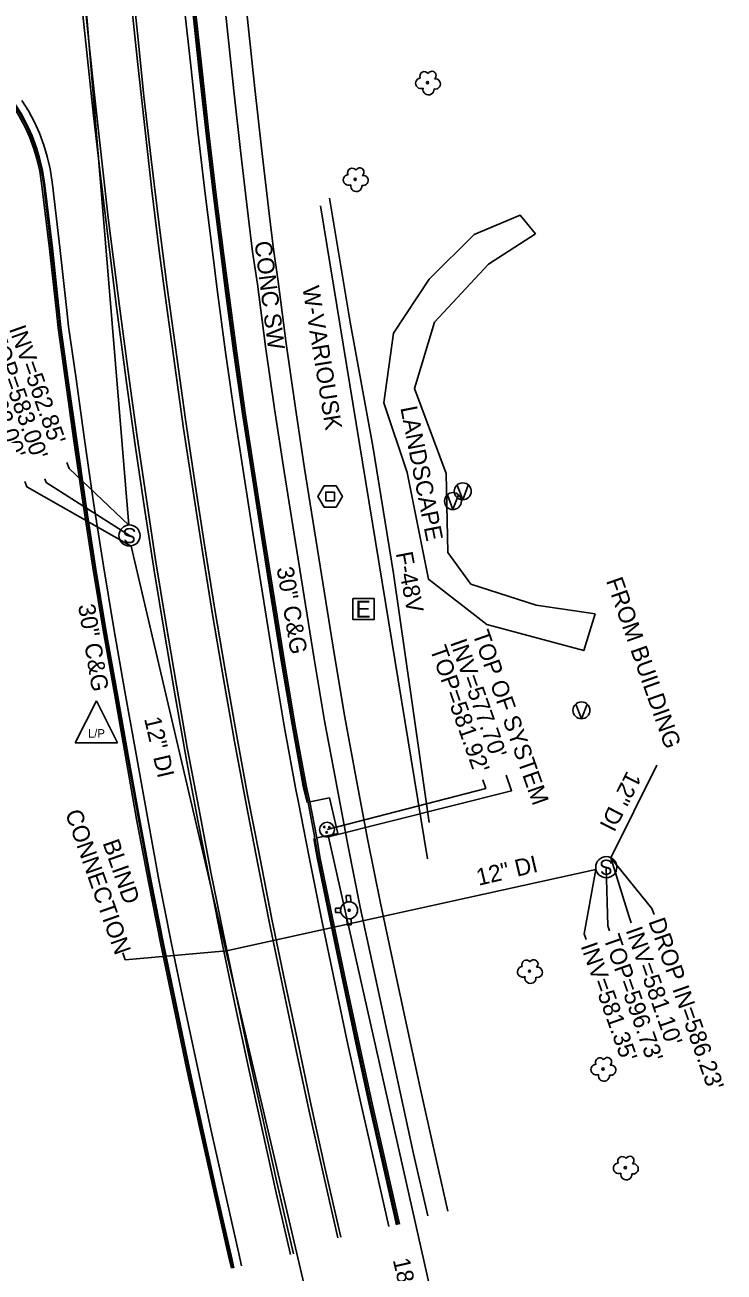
# Model space of a CAD drawing. Extents: x 2004847 to 2009016, y 1134161 to 1140101.
# Drawn here: x 2007523.7 to 2007689.1, y 1136946.2 to 1137241.2 of the extents above; entities that cross this region are included whole.
import ezdxf

# ---------------------------------------------------------------- set-up
doc = ezdxf.new("R2010")
doc.units = 0
for name, color, linetype in [('RD_EX_BldgApp', 7, 'Continuous'), ('RD_EX_Conc', 7, 'Continuous'), ('RD_EX_Curb', 7, 'Continuous'), ('RD_EX_DR_Inlet', 7, 'Continuous'), ('RD_EX_DR_Inlet_txCode', 7, 'Continuous'), ('RD_EX_DR_Pipe', 7, 'Continuous'), ('RD_EX_DR_Pipe_txCode', 7, 'Continuous'), ('RD_EX_Fence_Other', 7, 'Continuous'), ('RD_EX_Pavement_Markings', 7, 'Continuous'), ('RD_EX_Road', 7, 'Continuous'), ('RD_EX_SU_Elec', 7, 'Continuous'), ('RD_EX_SU_Sewer', 7, 'Continuous'), ('RD_EX_UT', 7, 'Continuous'), ('RD_EX_VEG', 7, 'Continuous'), ('RD_Sketch2', 7, 'Continuous'), ('RD_Sketch3', 7, 'Continuous')]:
    doc.layers.add(name, color=color, linetype=linetype)

msp = doc.modelspace()

# ---------------------------------------------------------------- linework, layer by layer
at = {"layer": 'RD_EX_BldgApp'}
msp.add_line((2007593.63, 1137198.39), (2007618.92, 1137043.93), dxfattribs=at)
at = {"layer": 'RD_EX_Conc'}
for points in [[(2007558.31, 1137480.41), (2007558.45, 1137464.24), (2007558.81, 1137449.33), (2007559.15, 1137434.3), (2007559.62, 1137419.34), (2007560.18, 1137404.46), (2007560.79, 1137389.52), (2007561.42, 1137374.51), (2007562.14, 1137359.65), (2007562.95, 1137344.71), (2007563.94, 1137329.81), (2007564.94, 1137314.87), (2007565.97, 1137299.95), (2007567.23, 1137285.11), (2007568.58, 1137270.25), (2007569.98, 1137255.36), (2007571.54, 1137240.53), (2007573.09, 1137225.63), (2007574.74, 1137210.79), (2007576.47, 1137195.99), (2007577.55, 1137187.51)], [(2007563.28, 1137480.5), (2007563.48, 1137464.33), (2007563.84, 1137449.47), (2007564.18, 1137434.42), (2007564.65, 1137419.48), (2007565.21, 1137404.66), (2007565.82, 1137389.74), (2007566.45, 1137374.72), (2007567.17, 1137359.93), (2007567.96, 1137345.01), (2007568.94, 1137330.15), (2007569.95, 1137315.22), (2007570.98, 1137300.32), (2007572.22, 1137285.54), (2007573.56, 1137270.71), (2007574.96, 1137255.84), (2007576.52, 1137241.07), (2007578.07, 1137226.17), (2007579.71, 1137211.37), (2007581.44, 1137196.62), (2007582.52, 1137188.15)], [(2007582.52, 1137188.15), (2007583.58, 1137180.52), (2007585.5, 1137165.85), (2007587.61, 1137151.12), (2007589.83, 1137136.3), (2007592.18, 1137121.52), (2007594.54, 1137106.79), (2007596.91, 1137092.03), (2007599.35, 1137077.45), (2007602.04, 1137062.9), (2007604.81, 1137048.24), (2007607.82, 1137033.46), (2007610.88, 1137019.01), (2007614.04, 1137004.33), (2007617.22, 1136989.76), (2007620.42, 1136975.26), (2007623.73, 1136960.59)], [(2007577.55, 1137187.51), (2007578.71, 1137179.88), (2007580.64, 1137165.14), (2007582.76, 1137150.37), (2007584.99, 1137135.55), (2007587.37, 1137120.76), (2007589.74, 1137106), (2007592.14, 1137091.23), (2007594.58, 1137076.58), (2007597.28, 1137061.96), (2007600.06, 1137047.28), (2007603.03, 1137032.52), (2007606.11, 1137017.99), (2007609.27, 1137003.32), (2007612.43, 1136988.72), (2007615.64, 1136974.17), (2007618.96, 1136959.52)]]:
    msp.add_lwpolyline(points, dxfattribs=at)
at = {"layer": 'RD_EX_Curb'}
for points in [[(2007550.81, 1137479.12), (2007551.12, 1137464.1), (2007551.5, 1137449.1), (2007551.98, 1137438.47), (2007552.01, 1137429.88), (2007552.15, 1137424.54), (2007552.7, 1137409.6), (2007553.29, 1137394.72), (2007553.95, 1137379.73), (2007554.58, 1137364.86), (2007555.4, 1137349.97), (2007556.32, 1137334.99), (2007557.25, 1137320.19), (2007558.28, 1137305.15), (2007559.41, 1137290.45), (2007560.7, 1137275.43), (2007562.08, 1137260.68), (2007563.51, 1137245.88), (2007565.14, 1137231.01), (2007566.76, 1137216.22), (2007568.45, 1137201.47), (2007570.35, 1137186.59)], [(2007551.27, 1137479.12), (2007551.55, 1137464.1), (2007551.87, 1137449.11), (2007552.45, 1137438.48), (2007552.45, 1137429.9), (2007552.6, 1137424.55), (2007553.12, 1137409.62), (2007553.7, 1137394.74), (2007554.33, 1137379.75), (2007554.95, 1137364.88), (2007555.78, 1137349.99), (2007556.71, 1137335.02), (2007557.64, 1137320.22), (2007558.68, 1137305.17), (2007559.77, 1137290.48), (2007561.07, 1137275.46), (2007562.46, 1137260.71), (2007563.92, 1137245.92), (2007565.54, 1137231.05), (2007567.15, 1137216.27), (2007568.87, 1137201.52), (2007570.75, 1137186.64)], [(2007551.87, 1137429.88), (2007551.87, 1137428.58), (2007551.89, 1137424.53), (2007552.41, 1137409.59), (2007552.99, 1137394.7), (2007553.66, 1137379.72), (2007554.31, 1137364.85), (2007555.14, 1137349.95), (2007556.04, 1137334.98), (2007556.98, 1137320.17), (2007558.02, 1137305.13), (2007559.1, 1137290.43), (2007560.47, 1137275.42), (2007561.84, 1137260.66), (2007563.26, 1137245.85), (2007564.86, 1137230.98), (2007566.47, 1137216.19), (2007568.19, 1137201.44), (2007570.08, 1137186.56)], [(2007489.11, 1137238.88), (2007490.91, 1137238.71), (2007493.9, 1137238.39), (2007496.5, 1137237.98), (2007499.11, 1137237.45), (2007501.98, 1137236.61), (2007504.36, 1137235.61), (2007506.81, 1137234.47), (2007509.43, 1137233), (2007511.35, 1137231.71), (2007513.36, 1137230.22), (2007515.59, 1137228.2), (2007517.5, 1137226.19), (2007519.11, 1137224.37), (2007520.88, 1137221.94), (2007522.34, 1137219.64), (2007523.74, 1137216.99), (2007524.75, 1137214.69), (2007525.78, 1137211.87), (2007526.48, 1137209.5), (2007527.2, 1137206.58), (2007527.73, 1137203.15)], [(2007489.14, 1137239.31), (2007490.96, 1137239.14), (2007493.95, 1137238.82), (2007496.59, 1137238.41), (2007499.24, 1137237.89), (2007502.12, 1137237.04), (2007504.53, 1137236.03), (2007507.02, 1137234.87), (2007509.64, 1137233.4), (2007511.62, 1137232.08), (2007513.68, 1137230.54), (2007515.91, 1137228.52), (2007517.83, 1137226.49), (2007519.47, 1137224.6), (2007521.26, 1137222.19), (2007522.73, 1137219.85), (2007524.13, 1137217.2), (2007525.18, 1137214.85), (2007526.21, 1137212.03), (2007526.91, 1137209.59), (2007527.6, 1137206.67), (2007528.15, 1137203.2)], [(2007489.15, 1137239.52), (2007490.99, 1137239.37), (2007493.97, 1137239.05), (2007496.63, 1137238.64), (2007499.28, 1137238.05), (2007502.16, 1137237.21), (2007504.6, 1137236.18), (2007507.1, 1137235.02), (2007509.72, 1137233.56), (2007511.73, 1137232.21), (2007513.8, 1137230.66), (2007516.05, 1137228.67), (2007517.98, 1137226.63), (2007519.64, 1137224.72), (2007521.44, 1137222.31), (2007522.93, 1137219.96), (2007524.34, 1137217.32), (2007525.39, 1137214.93), (2007526.42, 1137212.12), (2007527.13, 1137209.64), (2007527.87, 1137206.73), (2007528.4, 1137203.23)], [(2007531.16, 1137173.35), (2007529.48, 1137188.26), (2007527.73, 1137203.15)], [(2007531.59, 1137173.4), (2007529.87, 1137188.3), (2007528.15, 1137203.2)], [(2007531.82, 1137173.43), (2007530.23, 1137188.35), (2007528.4, 1137203.23)], [(2007570.08, 1137186.56), (2007571.06, 1137178.88), (2007573, 1137164.06), (2007575.14, 1137149.3), (2007577.41, 1137134.59), (2007579.71, 1137119.81), (2007582.02, 1137105.14), (2007584.42, 1137090.4), (2007586.87, 1137075.69), (2007589.52, 1137061.12), (2007590.47, 1137057.26)], [(2007570.35, 1137186.59), (2007571.34, 1137178.92), (2007573.32, 1137164.11), (2007575.43, 1137149.34), (2007577.7, 1137134.64), (2007579.99, 1137119.85), (2007582.33, 1137105.2), (2007584.72, 1137090.45), (2007587.12, 1137075.74), (2007589.8, 1137061.17), (2007590.66, 1137057.3), (2007592.28, 1137048.81), (2007593.09, 1137044.33), (2007596.05, 1137029.8), (2007599.16, 1137015.16), (2007602.25, 1137000.49), (2007605.43, 1136985.94), (2007608.75, 1136971.39), (2007611.9, 1136957.47)], [(2007570.75, 1137186.64), (2007571.76, 1137178.98), (2007573.72, 1137164.16), (2007575.83, 1137149.4), (2007578.09, 1137134.69), (2007580.36, 1137119.91), (2007582.72, 1137105.26), (2007585.1, 1137090.52), (2007587.52, 1137075.81), (2007590.2, 1137061.25), (2007591.09, 1137057.38), (2007592.71, 1137048.9), (2007593.49, 1137044.41), (2007596.44, 1137029.88), (2007599.54, 1137015.24), (2007602.64, 1137000.57), (2007605.81, 1136986.03), (2007609.11, 1136971.48), (2007612.26, 1136957.55)], [(2007572.55, 1136947.08), (2007571.87, 1136950), (2007568.52, 1136964.72), (2007565.21, 1136979.42), (2007562.02, 1136994.13), (2007558.91, 1137008.94), (2007555.85, 1137023.69), (2007552.92, 1137038.51), (2007550.12, 1137053.33), (2007547.48, 1137068.23), (2007544.86, 1137083.08), (2007542.23, 1137097.99), (2007539.78, 1137112.84), (2007537.5, 1137127.85), (2007535.3, 1137142.79), (2007533.25, 1137157.66), (2007531.57, 1137169.55), (2007531.16, 1137173.35)], [(2007572.86, 1136947.15), (2007572.17, 1136950.07), (2007568.83, 1136964.79), (2007565.56, 1136979.49), (2007562.39, 1136994.21), (2007559.28, 1137009.02), (2007556.24, 1137023.77), (2007553.32, 1137038.58), (2007550.54, 1137053.4), (2007547.85, 1137068.3), (2007545.22, 1137083.15), (2007542.59, 1137098.05), (2007540.14, 1137112.9), (2007537.86, 1137127.9), (2007535.69, 1137142.84), (2007533.59, 1137157.71), (2007531.92, 1137169.6), (2007531.59, 1137173.4)], [(2007573.13, 1136947.22), (2007572.46, 1136950.14), (2007569.11, 1136964.86), (2007565.83, 1136979.55), (2007562.66, 1136994.27), (2007559.53, 1137009.07), (2007556.51, 1137023.82), (2007553.58, 1137038.63), (2007550.81, 1137053.45), (2007548.13, 1137068.35), (2007545.5, 1137083.19), (2007542.87, 1137098.09), (2007540.42, 1137112.94), (2007538.1, 1137127.94), (2007535.96, 1137142.88), (2007533.86, 1137157.74), (2007532.18, 1137169.64), (2007531.82, 1137173.43)], [(2007592.05, 1137048.77), (2007592.82, 1137044.28), (2007595.8, 1137029.74), (2007598.87, 1137015.1), (2007601.96, 1137000.43), (2007605.13, 1136985.88), (2007608.46, 1136971.33), (2007611.61, 1136957.4)]]:
    msp.add_lwpolyline(points, dxfattribs=at)
at = {"layer": 'RD_EX_DR_Inlet'}
msp.add_lwpolyline([(2007592.71, 1137048.9), (2007597.7, 1137049.94), (2007595.74, 1137058.34), (2007591.09, 1137057.38)], dxfattribs=at)
for centre, radius in [((2007595.16, 1137050.85), 1.75), ((2007594.49, 1137051.48), 0.175), ((2007595.07, 1137050.19), 0.175), ((2007595.72, 1137051.41), 0.175)]:
    msp.add_circle(centre, radius, dxfattribs=at)
at = {"layer": 'RD_EX_DR_Inlet_txCode'}
for points in [[(2007595.16, 1137050.85), (2007632.71, 1137060.61), (2007632, 1137062.63)], [(2007595.54, 1137049.14), (2007638.81, 1137060.03), (2007637.5, 1137063.73)]]:
    msp.add_lwpolyline(points, dxfattribs=at)
at = {"layer": 'RD_EX_DR_Pipe'}
msp.add_line((2007595.54, 1137049.14), (2007625.47, 1136915.9), dxfattribs=at)
at = {"layer": 'RD_EX_Fence_Other'}
msp.add_lwpolyline([(2007619.28, 1137052.52), (2007615.15, 1137081.84), (2007610.86, 1137111.43), (2007605.95, 1137141.53), (2007600.64, 1137170.91), (2007595.76, 1137200.2)], dxfattribs=at)
at = {"layer": 'RD_EX_Pavement_Markings'}
for points in [[(2007525.04, 1137479.85), (2007525.31, 1137464.85), (2007525.65, 1137449.86), (2007526.04, 1137434.86), (2007526.54, 1137419.87), (2007527.04, 1137404.88), (2007527.69, 1137389.89), (2007528.41, 1137374.91), (2007529.14, 1137359.93), (2007530.01, 1137344.95), (2007530.98, 1137329.98), (2007531.98, 1137315.02), (2007533.09, 1137300.06), (2007534.26, 1137285.1), (2007535.59, 1137270.16), (2007537.03, 1137255.23), (2007538.46, 1137240.3), (2007540.04, 1137225.38), (2007541.71, 1137210.48), (2007543.42, 1137195.58)], [(2007545.24, 1137175.04), (2007543.45, 1137189.93), (2007541.67, 1137204.83), (2007539.93, 1137219.73), (2007538.33, 1137234.64), (2007536.75, 1137249.56), (2007535.4, 1137264.5), (2007534.06, 1137279.44), (2007532.78, 1137294.38), (2007531.69, 1137309.34), (2007530.59, 1137324.3), (2007529.66, 1137339.27), (2007528.77, 1137354.25), (2007527.97, 1137369.23), (2007527.27, 1137384.21), (2007526.57, 1137399.19), (2007526.06, 1137414.18), (2007525.56, 1137429.18), (2007525.08, 1137444.17), (2007524.76, 1137459.16), (2007524.33, 1137478.6)], [(2007537.06, 1137479.03), (2007537.34, 1137463.84), (2007537.63, 1137448.84), (2007538.04, 1137433.85), (2007538.53, 1137418.85), (2007539.08, 1137403.86), (2007539.74, 1137388.88), (2007540.4, 1137373.89), (2007541.19, 1137358.91), (2007542.07, 1137343.94), (2007542.95, 1137328.97), (2007544, 1137314), (2007544.98, 1137299.01), (2007546.23, 1137284.09), (2007547.41, 1137269.13), (2007548.78, 1137254.2), (2007550.3, 1137239.27), (2007551.86, 1137224.35), (2007553.55, 1137209.45), (2007555.4, 1137194.56), (2007557.26, 1137179.68)], [(2007555.49, 1137187.09), (2007553.75, 1137201.99), (2007552.05, 1137216.89), (2007550.37, 1137231.8), (2007548.86, 1137246.72), (2007547.41, 1137261.65), (2007546.08, 1137276.59), (2007544.91, 1137291.55), (2007543.74, 1137306.5), (2007542.71, 1137321.47), (2007541.77, 1137336.44), (2007540.84, 1137351.41), (2007540.06, 1137366.39), (2007539.35, 1137381.37), (2007538.69, 1137396.36), (2007538.11, 1137411.35), (2007537.54, 1137426.34), (2007537.16, 1137441.33), (2007536.81, 1137456.33), (2007536.49, 1137471.32)], [(2007543.42, 1137195.58), (2007546.1, 1137174.67), (2007548.09, 1137159.17), (2007550.19, 1137144.32), (2007552.38, 1137129.48), (2007554.61, 1137114.65), (2007557.03, 1137099.84), (2007559.51, 1137085.05), (2007562.1, 1137070.27), (2007564.9, 1137055.54), (2007567.7, 1137040.8), (2007570.67, 1137026.1), (2007573.72, 1137011.41), (2007576.82, 1136996.73), (2007580.05, 1136982.09), (2007583.32, 1136967.45), (2007587.2, 1136950.47)], [(2007597.7, 1136954.25), (2007594.4, 1136968.88), (2007591.12, 1136983.52), (2007587.92, 1136998.17), (2007584.85, 1137012.86), (2007581.78, 1137027.54), (2007578.87, 1137042.25), (2007576.04, 1137056.98), (2007573.25, 1137071.72), (2007570.69, 1137086.5), (2007568.17, 1137101.29), (2007565.74, 1137116.09), (2007563.49, 1137130.92), (2007561.24, 1137145.75), (2007559.16, 1137160.61), (2007557.11, 1137175.47), (2007555.49, 1137187.09)], [(2007557.26, 1137179.68), (2007559.59, 1137162.71), (2007561.68, 1137147.86), (2007563.87, 1137133.02), (2007566.18, 1137118.2), (2007568.53, 1137103.39), (2007571.06, 1137088.6), (2007573.65, 1137073.83), (2007576.34, 1137059.07), (2007579.23, 1137044.35), (2007582.12, 1137029.63), (2007585.2, 1137014.95), (2007588.31, 1137000.28), (2007591.42, 1136985.6), (2007594.66, 1136970.96), (2007598.41, 1136954.41)], [(2007586.53, 1136950.32), (2007583.14, 1136964.93), (2007579.86, 1136979.57), (2007576.64, 1136994.22), (2007573.47, 1137008.88), (2007570.44, 1137023.57), (2007567.48, 1137038.28), (2007564.63, 1137053), (2007561.86, 1137067.75), (2007559.23, 1137082.51), (2007556.7, 1137097.3), (2007554.3, 1137112.1), (2007551.96, 1137126.92), (2007549.81, 1137141.77), (2007547.76, 1137156.63), (2007545.24, 1137175.04)]]:
    msp.add_lwpolyline(points, dxfattribs=at)
at = {"layer": 'RD_EX_Road'}
for points in [[(2007548.7, 1137479.1), (2007548.94, 1137464.06), (2007549.36, 1137449.06), (2007549.7, 1137438.4), (2007549.91, 1137429.82), (2007550.15, 1137424.47), (2007550.57, 1137409.52), (2007551.16, 1137394.62), (2007551.82, 1137379.64), (2007552.44, 1137364.75), (2007553.27, 1137349.84), (2007554.15, 1137334.87), (2007555.14, 1137320.04), (2007556.18, 1137305.01), (2007557.27, 1137290.27), (2007558.55, 1137275.27), (2007559.93, 1137260.48), (2007561.38, 1137245.66), (2007562.98, 1137230.78), (2007564.59, 1137215.98), (2007566.31, 1137201.2), (2007568.21, 1137186.33)], [(2007522.99, 1137223.32), (2007524.55, 1137220.85), (2007525.95, 1137218.2), (2007527.12, 1137215.59), (2007528.16, 1137212.78), (2007528.97, 1137210.05), (2007529.7, 1137207.14), (2007530.23, 1137203.45)], [(2007533.63, 1137173.65), (2007531.93, 1137188.55), (2007530.23, 1137203.45)], [(2007568.21, 1137186.33), (2007569.2, 1137178.63), (2007571.15, 1137163.8), (2007573.3, 1137149.03), (2007575.57, 1137134.3), (2007577.87, 1137119.52), (2007580.18, 1137104.83), (2007582.59, 1137090.08), (2007585.05, 1137075.36), (2007587.71, 1137060.76), (2007588.47, 1137056.86), (2007590.12, 1137048.39), (2007591.03, 1137043.93), (2007593.89, 1137029.35), (2007597.01, 1137014.71), (2007600.11, 1137000.03), (2007603.29, 1136985.47), (2007606.62, 1136970.91), (2007609.77, 1136956.98)], [(2007574.96, 1136947.64), (2007574.29, 1136950.56), (2007570.95, 1136965.27), (2007567.7, 1136979.96), (2007564.49, 1136994.67), (2007561.36, 1137009.44), (2007558.31, 1137024.19), (2007555.39, 1137038.98), (2007552.65, 1137053.8), (2007549.98, 1137068.67), (2007547.35, 1137083.51), (2007544.72, 1137098.39), (2007542.28, 1137113.23), (2007539.94, 1137128.2), (2007537.8, 1137143.13), (2007535.7, 1137157.99), (2007534.02, 1137169.89), (2007533.63, 1137173.65)]]:
    msp.add_lwpolyline(points, dxfattribs=at)
at = {"layer": 'RD_EX_SU_Elec'}
msp.add_lwpolyline([(2007606.29, 1137105.51), (2007601.29, 1137105.51), (2007601.29, 1137100.51), (2007606.29, 1137100.51)], close=True, dxfattribs=at)
at = {"layer": 'RD_EX_SU_Sewer'}
for points in [[(2007598.78, 1137129.65), (2007597.34, 1137132.15), (2007594.45, 1137132.15), (2007593.01, 1137129.65), (2007594.45, 1137127.15), (2007597.34, 1137127.15)], [(2007596.91, 1137130.67), (2007594.87, 1137130.67), (2007594.87, 1137128.63), (2007596.91, 1137128.63)]]:
    msp.add_lwpolyline(points, close=True, dxfattribs=at)
for centre in [(2007548.44, 1137120.4), (2007661.21, 1137041.95)]:
    msp.add_circle(centre, 2.5, dxfattribs=at)
at = {"layer": 'RD_EX_UT'}
for p, q in [((2007548.24, 1137122.89), (2007515.63, 1137518.58)), ((2007627.25, 1137128.88), (2007625.94, 1137132.36)), ((2007627.25, 1137128.88), (2007628.57, 1137132.33)), ((2007624.94, 1137126.57), (2007623.64, 1137130.05)), ((2007624.94, 1137126.57), (2007626.27, 1137130.01)), ((2007636.73, 1136742.16), (2007548.86, 1137117.93)), ((2007535.61, 1137071.34), (2007540.61, 1137081.34)), ((2007540.61, 1137081.34), (2007545.61, 1137071.34)), ((2007655.33, 1137077.07), (2007654.03, 1137080.55)), ((2007655.33, 1137077.07), (2007656.65, 1137080.52)), ((2007535.61, 1137071.34), (2007545.61, 1137071.34)), ((2007662.32, 1137044.19), (2007673.18, 1137066.09)), ((2007658.77, 1137041.41), (2007571.37, 1137022.16)), ((2007600.71, 1137035.3), (2007599.71, 1137035.28)), ((2007599.71, 1137035.28), (2007599.75, 1137033.67)), ((2007600.75, 1137033.73), (2007600.71, 1137035.3)), ((2007598.44, 1137032.26), (2007597.14, 1137032.23)), ((2007597.14, 1137032.23), (2007597.17, 1137031.23)), ((2007597.17, 1137031.23), (2007598.44, 1137031.26)), ((2007599.85, 1137029.84), (2007599.9, 1137028.28)), ((2007600.9, 1137028.31), (2007600.86, 1137029.82)), ((2007599.9, 1137028.28), (2007600.9, 1137028.31))]:
    msp.add_line(p, q, dxfattribs=at)
for centre, radius in [((2007627.25, 1137130.87), 2), ((2007624.94, 1137128.56), 2), ((2007655.33, 1137079.06), 2), ((2007600.38, 1137031.77), 2), ((2007600.38, 1137031.77), 0.25)]:
    msp.add_circle(centre, radius, dxfattribs=at)
for start, end in [(165.7537, 194.721), (79.1932, 108.1695), (254.8469, 283.8232)]:
    msp.add_arc((2007600.38, 1137031.77), 2, start, end, dxfattribs=at)
at = {"layer": 'RD_EX_VEG'}
for points in [[(2007644.43, 1137191.75), (2007640.81, 1137196.21), (2007629.92, 1137191.62), (2007619.32, 1137181.08), (2007610.89, 1137168.28), (2007608.57, 1137151.8), (2007614.08, 1137135.33), (2007619.12, 1137110.05), (2007632.99, 1137099.39), (2007655.88, 1137093.21), (2007658.54, 1137101.89)], [(2007644.43, 1137191.75), (2007633.37, 1137184.63), (2007620.58, 1137170.86), (2007615.83, 1137155.17), (2007623.33, 1137135.1), (2007623.71, 1137116.43), (2007629.17, 1137108.94), (2007644.6, 1137103.96), (2007658.54, 1137101.89)]]:
    msp.add_lwpolyline(points, dxfattribs=at)
for centre in [(2007618.92, 1137227.52), (2007601.83, 1137204.67), (2007643.03, 1137017.38), (2007660.42, 1136994.23), (2007665.72, 1136970.89)]:
    msp.add_circle(centre, 0.25, dxfattribs=at)
for centre, radius, start, end in [((2007618.19, 1137229.07), 1.08, 34.9763, 204.756), ((2007619.96, 1137229.22), 0.995, 308.7626, 152.0467), ((2007617.35, 1137227.37), 1.26, 96.4518, 294.734), ((2007619.16, 1137225.93), 1.32, 166.8827, 5.7589), ((2007620.75, 1137227.24), 1.22, 256.5667, 98.1046), ((2007600.27, 1137204.51), 1.26, 96.4518, 294.734), ((2007601.11, 1137206.21), 1.08, 34.9763, 204.756), ((2007602.88, 1137206.37), 0.995, 308.7626, 152.0467), ((2007603.67, 1137204.39), 1.22, 256.5667, 98.1046), ((2007602.08, 1137203.07), 1.32, 166.8827, 5.7589), ((2007642.31, 1137018.93), 1.08, 34.9763, 204.756), ((2007644.07, 1137019.08), 0.995, 308.7626, 152.0467), ((2007641.46, 1137017.23), 1.26, 96.4518, 294.734), ((2007644.87, 1137017.1), 1.22, 256.5667, 98.1046), ((2007643.27, 1137015.79), 1.32, 166.8827, 5.7589), ((2007659.7, 1136995.78), 1.08, 34.9763, 204.756), ((2007661.46, 1136995.94), 0.995, 308.7626, 152.0467), ((2007658.85, 1136994.08), 1.26, 96.4518, 294.734), ((2007662.26, 1136993.95), 1.22, 256.5667, 98.1046), ((2007660.66, 1136992.64), 1.32, 166.8827, 5.7589), ((2007665, 1136972.43), 1.08, 34.9763, 204.756), ((2007666.76, 1136972.59), 0.995, 308.7626, 152.0467), ((2007664.15, 1136970.73), 1.26, 96.4518, 294.734), ((2007665.96, 1136969.29), 1.32, 166.8827, 5.7589), ((2007667.56, 1136970.61), 1.22, 256.5667, 98.1046)]:
    msp.add_arc(centre, radius, start, end, dxfattribs=at)
at = {"layer": 'RD_Sketch2'}
for points in [[(2007548.24, 1137122.89), (2007534.13, 1137136.3), (2007533.62, 1137137.72)], [(2007548.86, 1137117.93), (2007524.15, 1137131.9), (2007523.7, 1137133.17)], [(2007548.44, 1137120.4), (2007528.71, 1137132.99), (2007528.43, 1137133.8)], [(2007662.32, 1137044.19), (2007666.51, 1137030.46), (2007667.1, 1137028.8)], [(2007662.32, 1137044.19), (2007672, 1137032.2), (2007672.52, 1137030.75)], [(2007658.77, 1137041.41), (2007656, 1137026.2), (2007656.47, 1137024.87)], [(2007661.21, 1137041.95), (2007661.58, 1137028.06), (2007661.99, 1137026.89)], [(2007571.37, 1137022.16), (2007547.43, 1137020.06), (2007546.86, 1137021.68)]]:
    msp.add_lwpolyline(points, dxfattribs=at)

# ---------------------------------------------------------------- texts
at = {"layer": 'RD_EX_DR_Inlet_txCode'}
for s, p in [('TOP OF SYSTEM', (2007629.51, 1137097.2)), ("TOP=581.92'", (2007619.45, 1137093.57)), ("INV=577.70'", (2007624.21, 1137095.14))]:
    msp.add_text(s, height=4, rotation=289.4494, dxfattribs=at).set_placement(p)
at = {"layer": 'RD_EX_DR_Pipe_txCode'}
msp.add_text('18" RC', height=4, rotation=282.7848, dxfattribs=at).set_placement((2007610.7, 1136949.07))
at = {"layer": 'RD_EX_SU_Elec'}
msp.add_text('E', height=4, dxfattribs=at).set_placement((2007601.91, 1137101.01))
at = {"layer": 'RD_EX_SU_Sewer'}
for p in [(2007550.06, 1137122.18), (2007662.82, 1137043.74)]:
    msp.add_text('S', height=3.57, rotation=180, dxfattribs=at).set_placement(p)
at = {"layer": 'RD_EX_UT'}
msp.add_text('L/P', height=2, dxfattribs=at).set_placement((2007538.6, 1137072.62))
at = {"layer": 'RD_Sketch2'}
for s, rotation, p in [("INV=562.85'", 289.4494, (2007519.89, 1137169.32)), ("TOP=583.00'", 289.4494, (2007515, 1137167.72)), ("INV=563.00'", 289.4494, (2007510.45, 1137166.05)), ('FROM BUILDING', 289.4494, (2007661.11, 1137109.71)), ('12" DI', 283.2584, (2007551.86, 1137077.09)), ('12" DI', 243.0026, (2007666.16, 1137064.96)), ('CONNECTION', 289.4494, (2007533.15, 1137054.81)), ('BLIND', 289.4494, (2007542.01, 1137047.72)), ('12" DI', 13.2584, (2007631, 1137037.55)), ("DROP IN=586.23'", 289.4494, (2007671.13, 1137029.16)), ("TOP=596.73'", 289.4494, (2007660.49, 1137025.23)), ("INV=581.10'", 289.4494, (2007665.75, 1137027.06)), ("INV=581.35'", 289.4494, (2007655.1, 1137023.34))]:
    msp.add_text(s, height=4, rotation=rotation, dxfattribs=at).set_placement(p)
at = {"layer": 'RD_Sketch3'}
for s, rotation, p in [('CONC SW', 277.2318, (2007577.99, 1137189.84)), ('W-VARIOUSK', 279.2466, (2007589.3, 1137179.12)), ('LANDSCAPE', 281.0999, (2007612.48, 1137150.63)), ('F-48V', 280.7718, (2007611.4, 1137116.22)), ('30" C&G', 279.283, (2007583.22, 1137112.72)), ('30" C&G', 279.283, (2007536.25, 1137103.9))]:
    msp.add_text(s, height=4, rotation=rotation, dxfattribs=at).set_placement(p)

doc.saveas('drawing.dxf')
